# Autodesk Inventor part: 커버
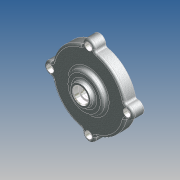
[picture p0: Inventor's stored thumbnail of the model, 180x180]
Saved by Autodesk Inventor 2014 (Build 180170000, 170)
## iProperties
Created: 2012-05
Part Number: 커버
Document SubType Name: 모델링
Designer: SeoGD™
Material: 알루미늄 6061
Density: 1 g/cm^3
Appearance: 알루미늄 캐스트
변환 표준: STEP AP214IS
파일 이름: C:\Users\SeoGD\Desktop\?쒗뿕\而ㅻ쾭-1.stp
전처리기: Build: 253, Release: 2010 SP1 - Date: Wed 07/29/2009
전송 단위: 밀리미터
불확실성: 0.01
Author: SeoGD™
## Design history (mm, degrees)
sketch "스케치1"
  geometry: L1 (0, 0)-(0, 26); L2 (50, 0)-(50, 15); L3 (50, 15)-(25, 15); L4 (25, 15)-(25, 21); L5 (25, 21)-(15, 21); L6 (15, 21)-(13.66, 26); L7 (13.66, 26)-(10, 26); L8 (50, 0)-(45, 0); L9 (45, 0)-(45, 10); L10 (45, 10)-(14.5, 10); L11 (14.5, 10)-(13.266, 3); L12 (13.266, 3)-(11, 3); L13 (11, 3)-(11, 16); L14 (11, 16)-(7.5, 16); L15 (7.5, 16)-(7.5, 19); L16 (7.5, 19)-(10, 19); L17 (10, 19)-(10, 26)
  constraints: 34 end point, 10 parallel, 2 perpendicular, 2 point on line, 1 vertical
  dimensions: "d11" = 100 diameter of L2 L1; "d12" = 22 diameter of L13 L1; "d13" = 90 diameter of L9 L1; "d14" = 15 distance between parallel lines of L3 L8; "d15" = 10 distance between parallel lines of L8 L10; "d16" = 29 diameter of L10.end L1; "d17" = 100 deg angle of L11 L10; "d18" = 7 distance between parallel lines of L12 L10; "d19" = 13 distance between parallel lines of L14 L12; "d20" = 3 distance between parallel lines of L16 L14; "d21" = 15 diameter of L15 L1; "d22" = 20 diameter of L17 L1; "d23" = 30 diameter of L5.end L1; "d24" = 6 distance between parallel lines of L5 L3; "d25" = 50 diameter of L4 L1; "d26" = 105 deg angle of L5 L6; "d50" = 26 distance of L1.start L1.end
revolve "회전1" sketch "스케치1" stored, may be unused: angle "d27" = 90 deg
sketch "스케치2" dims "d29" = 104
  geometry: A1 r 8.5 centre (0, 52) between (8.074, 49.344) and (-8.074, 49.344); A2 r 50 centre (0, 0) between (-8.074, 49.344) and (8.074, 49.344) reference; 2 further points
  constraints: 4 point on circle, 2 vertical alignment, 1 centre point, 1 coincident, 2 other
  dimensions: "d28" = 17 diameter of A1
extrude "돌출1" join sketch "스케치2" stored distance "d30" = 10; taper "d31" = 0 deg
fillet "모깎기3" dims "d32" = 3
fillet "모깎기4" dims "d45" = 3, "d46" = 0.2
chamfer "모따기1" distance "d47" = 1; stored, may be unused: second distance "d48" = 2, angle "d49" = 45 deg
hole "구멍2" diameter "d38" = 5.5; stored, may be unused: countersink angle "d42" = 90 deg, drill point angle "d44" = 118 deg; dims "d36" = 10, "d37" = 10, "d39" = 6, "d40" = 9.5, "d41" = 5.4, "d43" = 8
node "솔리드1"
node "솔리드 본체"
node "곡면 본체"
pattern_circular "원형 패턴1" dims angle "d34" = 360 deg
pattern_circular "원형 패턴2" dims angle "d52" = 360 deg
node "솔리드2"
